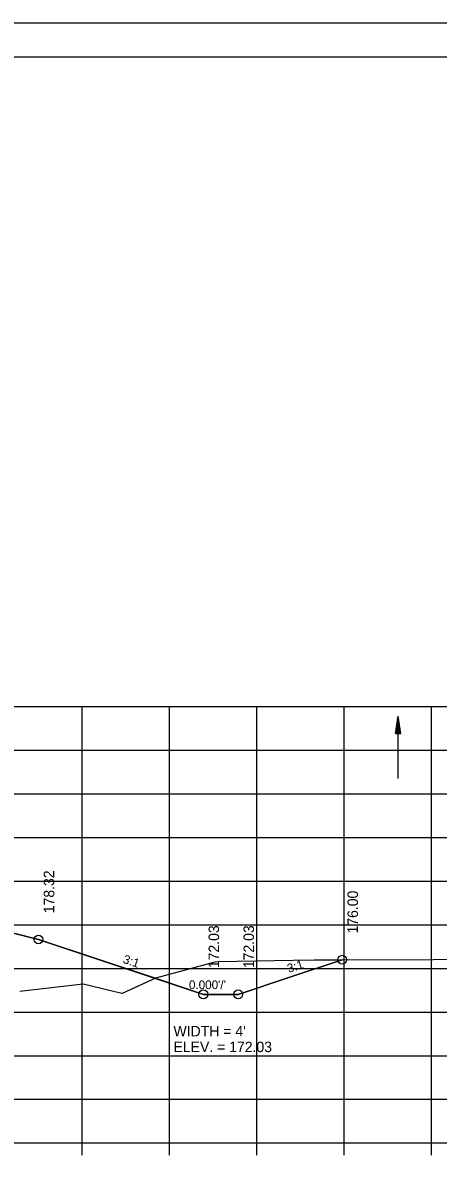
# Model space of a CAD drawing. Extents: x 1372132 to 1372465, y 380083 to 381790.
# Drawn here: x 1372325.2 to 1372372.8, y 380806.4 to 380936.8 of the extents above; entities that cross this region are included whole.
import ezdxf

# ---------------------------------------------------------------- set-up
doc = ezdxf.new("R2010")
doc.units = 0
for name, color, linetype in [('R_Axis', 7, 'Continuous'), ('R_Border', 7, 'Continuous'), ('R_Dimension', 7, 'Continuous'), ('R_Draft', 7, 'Continuous'), ('R_Exist Surface', 7, 'Continuous'), ('R_Fin Surface', 7, 'Continuous'), ('R_Grid', 7, 'Continuous'), ('R_No Plot', 7, 'Continuous'), ('R_Xsect Elev', 7, 'Continuous'), ('R_Xsect Slope', 7, 'Continuous')]:
    doc.layers.add(name, color=color, linetype=linetype)

msp = doc.modelspace()

# ---------------------------------------------------------------- linework, layer by layer
at = {"layer": 'R_Axis'}
for p, q in [((1372162.01, 380808.49), (1372442.01, 380808.49)), ((1372332.01, 380807.09), (1372332.01, 380808.49)), ((1372342.01, 380807.09), (1372342.01, 380808.49)), ((1372352.01, 380807.09), (1372352.01, 380808.49)), ((1372362.01, 380807.09), (1372362.01, 380808.49)), ((1372372.01, 380807.09), (1372372.01, 380808.49))]:
    msp.add_line(p, q, dxfattribs=at)
at = {"layer": 'R_Border'}
msp.add_line((1372144.01, 380932.95), (1372460.19, 380932.95), dxfattribs=at)
at = {"layer": 'R_Dimension'}
for p, q in [((1372367.91, 380855.4), (1372368.21, 380857.4)), ((1372367.91, 380855.4), (1372368.21, 380857.4)), ((1372367.96, 380855.4), (1372368.21, 380857.07)), ((1372367.96, 380855.4), (1372368.21, 380857.07)), ((1372368.01, 380855.4), (1372368.21, 380856.72)), ((1372368.01, 380855.4), (1372368.21, 380856.72)), ((1372368.51, 380855.4), (1372368.21, 380857.4)), ((1372368.51, 380855.4), (1372368.21, 380857.4)), ((1372368.46, 380855.4), (1372368.21, 380857.07)), ((1372368.46, 380855.4), (1372368.21, 380857.07)), ((1372368.41, 380855.4), (1372368.21, 380856.72)), ((1372368.41, 380855.4), (1372368.21, 380856.72)), ((1372367.91, 380855.4), (1372368.51, 380855.4)), ((1372367.91, 380855.4), (1372368.51, 380855.4)), ((1372368.06, 380855.4), (1372368.21, 380856.39)), ((1372368.06, 380855.4), (1372368.21, 380856.39)), ((1372368.11, 380855.4), (1372368.21, 380856.05)), ((1372368.11, 380855.4), (1372368.21, 380856.05)), ((1372368.16, 380855.4), (1372368.21, 380855.72)), ((1372368.16, 380855.4), (1372368.21, 380855.72)), ((1372368.36, 380855.4), (1372368.21, 380856.39)), ((1372368.36, 380855.4), (1372368.21, 380856.39)), ((1372368.31, 380855.4), (1372368.21, 380856.05)), ((1372368.31, 380855.4), (1372368.21, 380856.05)), ((1372368.26, 380855.4), (1372368.21, 380855.72)), ((1372368.26, 380855.4), (1372368.21, 380855.72))]:
    msp.add_line(p, q, dxfattribs=at)
at = {"layer": 'R_Draft'}
msp.add_line((1372368.21, 380850.26), (1372368.21, 380857.4), dxfattribs=at)
at = {"layer": 'R_Exist Surface'}
msp.add_lwpolyline([(1372324.87, 380825.89), (1372332.14, 380826.74), (1372336.55, 380825.67), (1372336.61, 380825.64), (1372336.64, 380825.65), (1372340.46, 380827.41), (1372347.24, 380829.25), (1372347.57, 380829.3), (1372356.18, 380829.44), (1372358.6, 380829.48), (1372372.24, 380829.52), (1372398.88, 380829.62), (1372408.83, 380829.55), (1372413.36, 380829.57), (1372422.06, 380829.56), (1372427.25, 380829.58), (1372435.35, 380829.58), (1372441.44, 380829.61), (1372442.01, 380829.61)], dxfattribs=at)
at = {"layer": 'R_Fin Surface'}
msp.add_lwpolyline([(1372245.35, 380825.16), (1372246.45, 380824.79), (1372254.45, 380824.79), (1372274.87, 380831.59), (1372282.65, 380833.22), (1372287.01, 380834.31), (1372291.01, 380834.47), (1372302.01, 380834.69), (1372313.01, 380834.47), (1372317.01, 380834.31), (1372321.38, 380833.22), (1372327.01, 380831.81), (1372345.89, 380825.52), (1372349.89, 380825.52), (1372355.81, 380827.49), (1372361.8, 380829.49)], dxfattribs=at)
at = {"layer": 'R_Grid'}
for p, q in [((1372162.01, 380858.49), (1372442.01, 380858.49)), ((1372332.01, 380808.49), (1372332.01, 380858.49)), ((1372342.01, 380808.49), (1372342.01, 380858.49)), ((1372352.01, 380808.49), (1372352.01, 380858.49)), ((1372362.01, 380808.49), (1372362.01, 380858.49)), ((1372372.01, 380808.49), (1372372.01, 380858.49)), ((1372162.01, 380853.49), (1372442.01, 380853.49)), ((1372162.01, 380848.49), (1372442.01, 380848.49)), ((1372162.01, 380843.49), (1372442.01, 380843.49)), ((1372162.01, 380838.49), (1372442.01, 380838.49)), ((1372162.01, 380833.49), (1372442.01, 380833.49)), ((1372162.01, 380828.49), (1372442.01, 380828.49)), ((1372162.01, 380823.49), (1372442.01, 380823.49)), ((1372162.01, 380818.49), (1372442.01, 380818.49)), ((1372162.01, 380813.49), (1372442.01, 380813.49)), ((1372162.01, 380808.49), (1372442.01, 380808.49))]:
    msp.add_line(p, q, dxfattribs=at)
at = {"layer": 'R_No Plot'}
msp.add_line((1372131.61, 380936.84), (1372464.95, 380936.84), dxfattribs=at)
for points in [[(1372131.61, 380936.84), (1372464.95, 380936.84), (1372464.95, 380723.5), (1372131.61, 380723.5)], [(1372377.93, 380932.95), (1372377.93, 380923.07), (1372413.67, 380923.07), (1372413.67, 380920.15), (1372436.87, 380920.15), (1372436.87, 380895.81), (1372460.19, 380895.81), (1372460.19, 380727.49), (1372144.01, 380727.49), (1372144.01, 380932.95)], [(1372340.36, 380827.36), (1372340.46, 380827.41), (1372347.24, 380829.25), (1372347.57, 380829.3), (1372356.18, 380829.44), (1372358.6, 380829.48), (1372361.8, 380829.49), (1372355.81, 380827.49), (1372349.89, 380825.52), (1372345.89, 380825.52)]]:
    msp.add_lwpolyline(points, close=True, dxfattribs=at)
msp.add_lwpolyline([(1372324.87, 380825.89), (1372332.14, 380826.74), (1372336.55, 380825.67), (1372336.61, 380825.64), (1372336.64, 380825.65), (1372340.36, 380827.36), (1372327.01, 380831.81), (1372321.38, 380833.22)], dxfattribs=at)
for centre in [(1372327.01, 380831.81), (1372361.8, 380829.49), (1372345.89, 380825.52), (1372349.89, 380825.52)]:
    msp.add_circle(centre, 0.5, dxfattribs=at)

# ---------------------------------------------------------------- texts
at = {"layer": 'R_Dimension'}
for s, p in [("WIDTH = 4'", (1372342.47, 380820.7)), ('ELEV. = 172.03', (1372342.47, 380818.9))]:
    msp.add_text(s, height=1.2, dxfattribs=at).set_placement(p)
at = {"layer": 'R_Xsect Elev'}
for s, p in [('178.32', (1372328.81, 380834.81)), ('176.00', (1372363.6, 380832.49)), ('172.03', (1372347.69, 380828.52)), ('172.03', (1372351.69, 380828.52))]:
    msp.add_text(s, height=1.2, rotation=90, dxfattribs=at).set_placement(p)
at = {"layer": 'R_Xsect Slope'}
for s, rotation, p in [('3:1', 341.5668, (1372336.61, 380829.14)), ('3:1', 18.4349, (1372355.69, 380827.97)), ("0.000'/'", 360, (1372344.24, 380826.12))]:
    msp.add_text(s, height=1, rotation=rotation, dxfattribs=at).set_placement(p)

doc.saveas('drawing.dxf')
